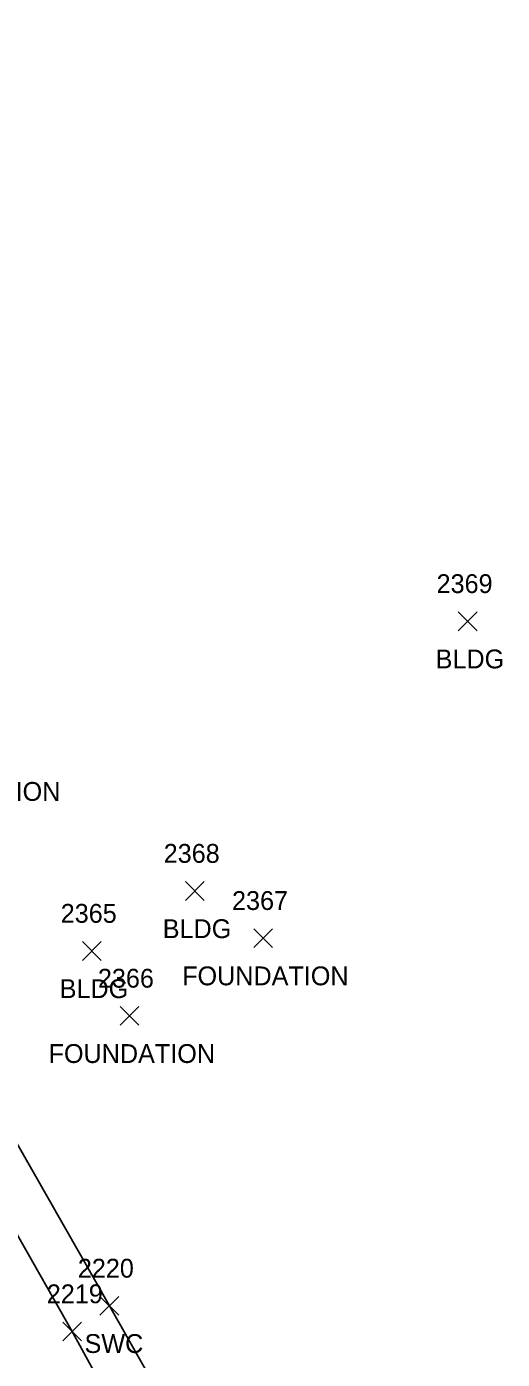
# Model space of a CAD drawing. Extents: x 1635588 to 1637550, y 621583 to 623638.
# Drawn here: x 1636586.9 to 1636637.5, y 622937 to 623078.5 of the extents above; entities that cross this region are included whole.
import ezdxf

# ---------------------------------------------------------------- set-up
doc = ezdxf.new("R2010")
doc.units = 0
for name, color, linetype in [('L_A', 7, 'Continuous'), ('L_I', 7, 'Continuous'), ('L_TIC', 7, 'Continuous'), ('P_I', 7, 'Continuous'), ('P_TIC', 7, 'Continuous'), ('PET', 7, 'Continuous'), ('R_A', 7, 'Continuous'), ('R_I', 7, 'Continuous'), ('R_TIC', 7, 'Continuous'), ('RSW', 7, 'Continuous')]:
    doc.layers.add(name, color=color, linetype=linetype)

msp = doc.modelspace()

# ---------------------------------------------------------------- linework, layer by layer
at = {"layer": 'L_TIC'}
for points in [[(1636632.78, 623014.37), (1636634.78, 623016.37)], [(1636634.78, 623014.37), (1636632.78, 623016.37)], [(1636603.79, 622985.72), (1636605.79, 622987.72)], [(1636605.79, 622985.72), (1636603.79, 622987.72)], [(1636611.04, 622980.71), (1636613.04, 622982.71)], [(1636613.04, 622980.71), (1636611.04, 622982.71)], [(1636592.84, 622979.35), (1636594.84, 622981.35)], [(1636594.84, 622979.35), (1636592.84, 622981.35)], [(1636596.85, 622972.46), (1636598.85, 622974.46)], [(1636598.85, 622972.46), (1636596.85, 622974.46)]]:
    msp.add_lwpolyline(points, dxfattribs=at)
at = {"layer": 'P_TIC'}
for points in [[(1636590.76, 622938.94), (1636592.76, 622940.94)], [(1636592.76, 622938.94), (1636590.76, 622940.94)]]:
    msp.add_lwpolyline(points, dxfattribs=at)
at = {"layer": 'PET'}
msp.add_lwpolyline([(1636524.76, 623078.53), (1636523.53, 623074.7), (1636523.65, 623069.69), (1636530.21, 623056.13), (1636548.33, 623020.32), (1636566.47, 622984.44), (1636591.76, 622939.94), (1636601.42, 622922.26), (1636608.34, 622909.96), (1636613.87, 622901.12), (1636616.68, 622897.25), (1636624.11, 622894.09), (1636627.52, 622895.36), (1636632.87, 622898.34)], dxfattribs=at)
at = {"layer": 'R_TIC'}
for points in [[(1636594.71, 622941.66), (1636596.71, 622943.66)], [(1636596.71, 622941.66), (1636594.71, 622943.66)]]:
    msp.add_lwpolyline(points, dxfattribs=at)
at = {"layer": 'RSW'}
msp.add_lwpolyline([(1636524.76, 623078.53), (1636528.35, 623071.35), (1636530.25, 623067.42), (1636534.71, 623058.46), (1636552.77, 623022.45), (1636571.37, 622985.37), (1636595.71, 622942.66), (1636605.64, 622925.15), (1636612.41, 622912.41), (1636617.8, 622903.4), (1636619.7, 622901.31), (1636620.99, 622899.9), (1636623.17, 622899.6), (1636625.06, 622899.88), (1636629.3, 622902.63)], dxfattribs=at)

# ---------------------------------------------------------------- texts
at = {"layer": 'L_A'}
for s, p in [('BLDG', (1636630.37, 623010.37)), ('FOUNDATION', (1636572.82, 622996.3)), ('BLDG', (1636601.38, 622981.72)), ('FOUNDATION', (1636603.44, 622976.71)), ('BLDG', (1636590.43, 622975.35)), ('FOUNDATION', (1636589.25, 622968.46))]:
    msp.add_text(s, height=2, dxfattribs=at).set_placement(p)
at = {"layer": 'L_I'}
for s, p in [('2369', (1636630.47, 623018.37)), ('2368', (1636601.48, 622989.72)), ('2367', (1636608.74, 622984.71)), ('2365', (1636590.54, 622983.35)), ('2366', (1636594.49, 622976.46))]:
    msp.add_text(s, height=2, dxfattribs=at).set_placement(p)
at = {"layer": 'P_I'}
msp.add_text('2219', height=2, dxfattribs=at).set_placement((1636589.06, 622942.94))
at = {"layer": 'R_A'}
msp.add_text('SWC', height=2, dxfattribs=at).set_placement((1636593.07, 622937.66))
at = {"layer": 'R_I'}
msp.add_text('2220', height=2, dxfattribs=at).set_placement((1636592.36, 622945.66))

doc.saveas('drawing.dxf')
